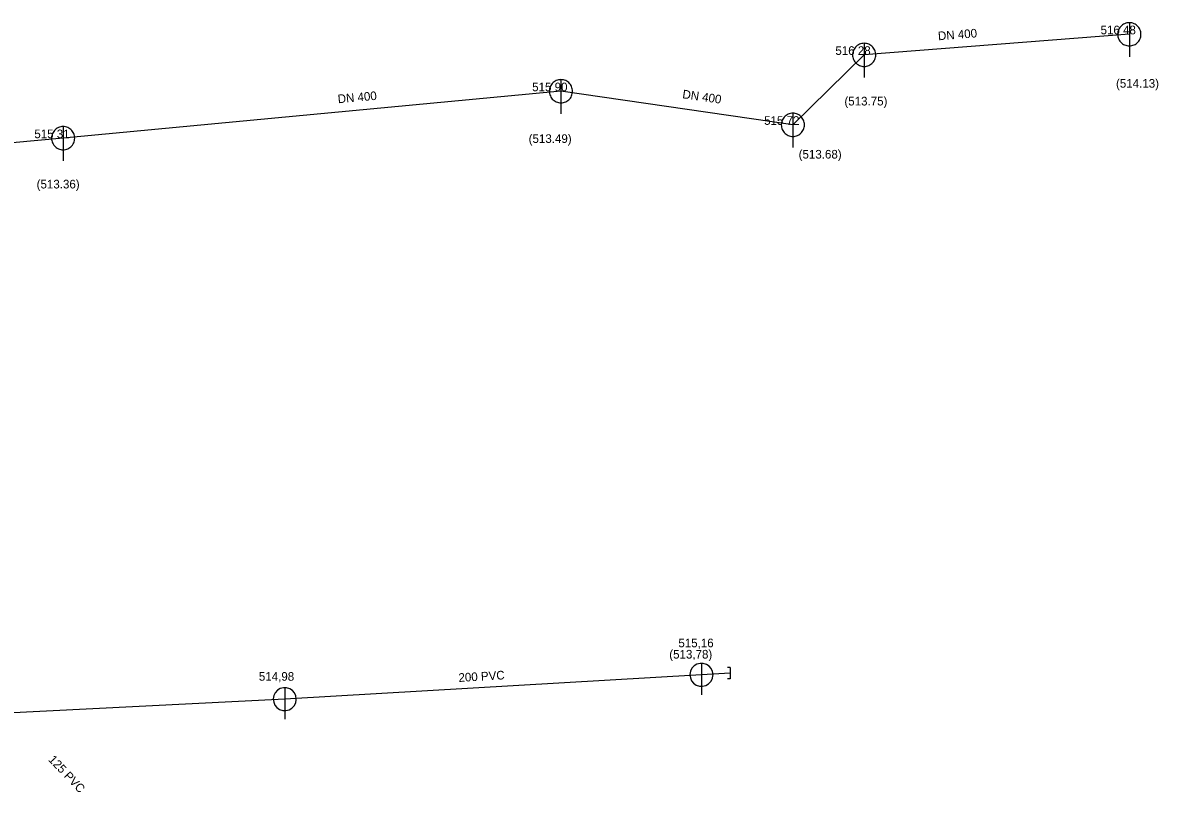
# Model space of a CAD drawing. Extents: x -476058 to -471893, y -1155786 to -1152000.
# Drawn here: x -474685.2 to -474586.5, y -1154195.9 to -1154129 of the extents above; entities that cross this region are included whole.
import ezdxf

# ---------------------------------------------------------------- set-up
doc = ezdxf.new("R2010")
doc.units = 0
for name, color, linetype in [('Vrstva 1', 7, 'Continuous'), ('Vrstva 10', 7, 'Continuous'), ('Vrstva 16', 7, 'Continuous'), ('Vrstva 18', 7, 'Continuous'), ('Vrstva 19', 7, 'Continuous'), ('Vrstva 3', 7, 'Continuous'), ('Vrstva 35', 7, 'Continuous'), ('Vrstva 4', 7, 'Continuous'), ('Vrstva 45', 7, 'Continuous')]:
    doc.layers.add(name, color=color, linetype=linetype)

msp = doc.modelspace()

# ---------------------------------------------------------------- linework, layer by layer
at = {"layer": 'Vrstva 1'}
for p, q in [((-474589.06, -1154130.02), (-474589.06, -1154130.02)), ((-474612.1, -1154131.81), (-474612.1, -1154131.81)), ((-474638.44, -1154134.97), (-474638.44, -1154134.97)), ((-474618.29, -1154137.89), (-474618.29, -1154137.89)), ((-474681.69, -1154139.05), (-474681.69, -1154139.05))]:
    msp.add_line(p, q, dxfattribs=at)
at = {"layer": 'Vrstva 10'}
for p, q in [((-474626.23, -1154184.69), (-474626.23, -1154187.438)), ((-474623.728, -1154185.044), (-474623.978, -1154185.044)), ((-474623.728, -1154185.044), (-474623.728, -1154186.044)), ((-474623.728, -1154186.044), (-474623.978, -1154186.044)), ((-474662.43, -1154186.81), (-474662.43, -1154189.558))]:
    msp.add_line(p, q, dxfattribs=at)
for points in [[(-474588.052, -1154130.02), (-474588.058, -1154129.915), (-474588.074, -1154129.811), (-474588.102, -1154129.709), (-474588.14, -1154129.61), (-474588.187, -1154129.516), (-474588.245, -1154129.428), (-474588.311, -1154129.346), (-474588.386, -1154129.271), (-474588.468, -1154129.205), (-474588.556, -1154129.147), (-474588.65, -1154129.1), (-474588.749, -1154129.062), (-474588.851, -1154129.034), (-474588.955, -1154129.018), (-474589.06, -1154129.012), (-474589.165, -1154129.018), (-474589.27, -1154129.034), (-474589.372, -1154129.062), (-474589.47, -1154129.1), (-474589.564, -1154129.147), (-474589.653, -1154129.205), (-474589.735, -1154129.271), (-474589.809, -1154129.346), (-474589.875, -1154129.428), (-474589.933, -1154129.516), (-474589.981, -1154129.61), (-474590.019, -1154129.709), (-474590.046, -1154129.811), (-474590.062, -1154129.915), (-474590.068, -1154130.02), (-474590.062, -1154130.125), (-474590.046, -1154130.23), (-474590.019, -1154130.332), (-474589.981, -1154130.43), (-474589.933, -1154130.524), (-474589.875, -1154130.613), (-474589.809, -1154130.695), (-474589.735, -1154130.769), (-474589.653, -1154130.835), (-474589.564, -1154130.893), (-474589.47, -1154130.941), (-474589.372, -1154130.979), (-474589.27, -1154131.006), (-474589.165, -1154131.022), (-474589.06, -1154131.028), (-474588.955, -1154131.022), (-474588.851, -1154131.006), (-474588.749, -1154130.979), (-474588.65, -1154130.941), (-474588.556, -1154130.893), (-474588.468, -1154130.835), (-474588.386, -1154130.769), (-474588.311, -1154130.695), (-474588.245, -1154130.613), (-474588.187, -1154130.524), (-474588.14, -1154130.43), (-474588.102, -1154130.332), (-474588.074, -1154130.23), (-474588.058, -1154130.125), (-474588.052, -1154130.02)], [(-474589.06, -1154129.012), (-474589.06, -1154131.988)], [(-474611.092, -1154131.81), (-474611.098, -1154131.705), (-474611.114, -1154131.601), (-474611.142, -1154131.499), (-474611.18, -1154131.4), (-474611.227, -1154131.306), (-474611.285, -1154131.218), (-474611.351, -1154131.136), (-474611.426, -1154131.061), (-474611.508, -1154130.995), (-474611.596, -1154130.937), (-474611.69, -1154130.89), (-474611.789, -1154130.852), (-474611.891, -1154130.824), (-474611.995, -1154130.808), (-474612.1, -1154130.802), (-474612.205, -1154130.808), (-474612.31, -1154130.824), (-474612.412, -1154130.852), (-474612.51, -1154130.89), (-474612.604, -1154130.937), (-474612.693, -1154130.995), (-474612.775, -1154131.061), (-474612.849, -1154131.136), (-474612.915, -1154131.218), (-474612.973, -1154131.306), (-474613.021, -1154131.4), (-474613.059, -1154131.499), (-474613.086, -1154131.601), (-474613.102, -1154131.705), (-474613.108, -1154131.81), (-474613.102, -1154131.915), (-474613.086, -1154132.02), (-474613.059, -1154132.122), (-474613.021, -1154132.22), (-474612.973, -1154132.314), (-474612.915, -1154132.403), (-474612.849, -1154132.485), (-474612.775, -1154132.559), (-474612.693, -1154132.625), (-474612.604, -1154132.683), (-474612.51, -1154132.731), (-474612.412, -1154132.769), (-474612.31, -1154132.796), (-474612.205, -1154132.812), (-474612.1, -1154132.818), (-474611.995, -1154132.812), (-474611.891, -1154132.796), (-474611.789, -1154132.769), (-474611.69, -1154132.731), (-474611.596, -1154132.683), (-474611.508, -1154132.625), (-474611.426, -1154132.559), (-474611.351, -1154132.485), (-474611.285, -1154132.403), (-474611.227, -1154132.314), (-474611.18, -1154132.22), (-474611.142, -1154132.122), (-474611.114, -1154132.02), (-474611.098, -1154131.915), (-474611.092, -1154131.81)], [(-474612.1, -1154130.802), (-474612.1, -1154133.778)], [(-474637.432, -1154134.97), (-474637.438, -1154134.865), (-474637.454, -1154134.761), (-474637.482, -1154134.659), (-474637.52, -1154134.56), (-474637.567, -1154134.466), (-474637.625, -1154134.378), (-474637.691, -1154134.296), (-474637.766, -1154134.221), (-474637.848, -1154134.155), (-474637.936, -1154134.097), (-474638.03, -1154134.05), (-474638.129, -1154134.012), (-474638.231, -1154133.984), (-474638.335, -1154133.968), (-474638.44, -1154133.962), (-474638.545, -1154133.968), (-474638.65, -1154133.984), (-474638.752, -1154134.012), (-474638.85, -1154134.05), (-474638.944, -1154134.097), (-474639.033, -1154134.155), (-474639.115, -1154134.221), (-474639.189, -1154134.296), (-474639.255, -1154134.378), (-474639.313, -1154134.466), (-474639.361, -1154134.56), (-474639.399, -1154134.659), (-474639.426, -1154134.761), (-474639.442, -1154134.865), (-474639.448, -1154134.97), (-474639.442, -1154135.075), (-474639.426, -1154135.18), (-474639.399, -1154135.282), (-474639.361, -1154135.38), (-474639.313, -1154135.474), (-474639.255, -1154135.563), (-474639.189, -1154135.645), (-474639.115, -1154135.719), (-474639.033, -1154135.785), (-474638.944, -1154135.843), (-474638.85, -1154135.891), (-474638.752, -1154135.929), (-474638.65, -1154135.956), (-474638.545, -1154135.972), (-474638.44, -1154135.978), (-474638.335, -1154135.972), (-474638.231, -1154135.956), (-474638.129, -1154135.929), (-474638.03, -1154135.891), (-474637.936, -1154135.843), (-474637.848, -1154135.785), (-474637.766, -1154135.719), (-474637.691, -1154135.645), (-474637.625, -1154135.563), (-474637.567, -1154135.474), (-474637.52, -1154135.38), (-474637.482, -1154135.282), (-474637.454, -1154135.18), (-474637.438, -1154135.075), (-474637.432, -1154134.97)], [(-474638.44, -1154133.962), (-474638.44, -1154136.938)], [(-474617.282, -1154137.89), (-474617.288, -1154137.785), (-474617.304, -1154137.681), (-474617.332, -1154137.579), (-474617.37, -1154137.48), (-474617.417, -1154137.386), (-474617.475, -1154137.298), (-474617.541, -1154137.216), (-474617.616, -1154137.141), (-474617.698, -1154137.075), (-474617.786, -1154137.017), (-474617.88, -1154136.97), (-474617.979, -1154136.932), (-474618.081, -1154136.904), (-474618.185, -1154136.888), (-474618.29, -1154136.882), (-474618.395, -1154136.888), (-474618.5, -1154136.904), (-474618.602, -1154136.932), (-474618.7, -1154136.97), (-474618.794, -1154137.017), (-474618.883, -1154137.075), (-474618.965, -1154137.141), (-474619.039, -1154137.216), (-474619.105, -1154137.298), (-474619.163, -1154137.386), (-474619.211, -1154137.48), (-474619.249, -1154137.579), (-474619.276, -1154137.681), (-474619.292, -1154137.785), (-474619.298, -1154137.89), (-474619.292, -1154137.995), (-474619.276, -1154138.1), (-474619.249, -1154138.202), (-474619.211, -1154138.3), (-474619.163, -1154138.394), (-474619.105, -1154138.483), (-474619.039, -1154138.565), (-474618.965, -1154138.639), (-474618.883, -1154138.705), (-474618.794, -1154138.763), (-474618.7, -1154138.811), (-474618.602, -1154138.849), (-474618.5, -1154138.876), (-474618.395, -1154138.892), (-474618.29, -1154138.898), (-474618.185, -1154138.892), (-474618.081, -1154138.876), (-474617.979, -1154138.849), (-474617.88, -1154138.811), (-474617.786, -1154138.763), (-474617.698, -1154138.705), (-474617.616, -1154138.639), (-474617.541, -1154138.565), (-474617.475, -1154138.483), (-474617.417, -1154138.394), (-474617.37, -1154138.3), (-474617.332, -1154138.202), (-474617.304, -1154138.1), (-474617.288, -1154137.995), (-474617.282, -1154137.89)], [(-474618.29, -1154136.882), (-474618.29, -1154139.858)], [(-474680.682, -1154139.05), (-474680.688, -1154138.945), (-474680.704, -1154138.841), (-474680.732, -1154138.739), (-474680.77, -1154138.64), (-474680.817, -1154138.546), (-474680.875, -1154138.458), (-474680.941, -1154138.376), (-474681.016, -1154138.301), (-474681.098, -1154138.235), (-474681.186, -1154138.177), (-474681.28, -1154138.13), (-474681.379, -1154138.092), (-474681.481, -1154138.064), (-474681.585, -1154138.048), (-474681.69, -1154138.042), (-474681.795, -1154138.048), (-474681.9, -1154138.064), (-474682.002, -1154138.092), (-474682.1, -1154138.13), (-474682.194, -1154138.177), (-474682.283, -1154138.235), (-474682.365, -1154138.301), (-474682.439, -1154138.376), (-474682.505, -1154138.458), (-474682.563, -1154138.546), (-474682.611, -1154138.64), (-474682.649, -1154138.739), (-474682.676, -1154138.841), (-474682.692, -1154138.945), (-474682.698, -1154139.05), (-474682.692, -1154139.155), (-474682.676, -1154139.26), (-474682.649, -1154139.362), (-474682.611, -1154139.46), (-474682.563, -1154139.554), (-474682.505, -1154139.643), (-474682.439, -1154139.725), (-474682.365, -1154139.799), (-474682.283, -1154139.865), (-474682.194, -1154139.923), (-474682.1, -1154139.971), (-474682.002, -1154140.009), (-474681.9, -1154140.036), (-474681.795, -1154140.052), (-474681.69, -1154140.058), (-474681.585, -1154140.052), (-474681.481, -1154140.036), (-474681.379, -1154140.009), (-474681.28, -1154139.971), (-474681.186, -1154139.923), (-474681.098, -1154139.865), (-474681.016, -1154139.799), (-474680.941, -1154139.725), (-474680.875, -1154139.643), (-474680.817, -1154139.554), (-474680.77, -1154139.46), (-474680.732, -1154139.362), (-474680.704, -1154139.26), (-474680.688, -1154139.155), (-474680.682, -1154139.05)], [(-474681.69, -1154138.042), (-474681.69, -1154141.018)], [(-474625.23, -1154185.69), (-474625.269, -1154185.411), (-474625.386, -1154185.154), (-474625.569, -1154184.939), (-474625.805, -1154184.785), (-474626.075, -1154184.702), (-474626.357, -1154184.698), (-474626.629, -1154184.773), (-474626.869, -1154184.921), (-474627.059, -1154185.13), (-474627.182, -1154185.384), (-474627.23, -1154185.662), (-474627.198, -1154185.943), (-474627.089, -1154186.203), (-474626.911, -1154186.422), (-474626.68, -1154186.584), (-474626.412, -1154186.674), (-474626.13, -1154186.686), (-474625.856, -1154186.618), (-474625.612, -1154186.477), (-474625.417, -1154186.273), (-474625.287, -1154186.023), (-474625.231, -1154185.746), (-474625.23, -1154185.69)], [(-474661.43, -1154187.81), (-474661.469, -1154187.531), (-474661.586, -1154187.274), (-474661.769, -1154187.059), (-474662.005, -1154186.905), (-474662.275, -1154186.822), (-474662.557, -1154186.818), (-474662.829, -1154186.893), (-474663.069, -1154187.041), (-474663.259, -1154187.25), (-474663.382, -1154187.504), (-474663.43, -1154187.782), (-474663.398, -1154188.063), (-474663.289, -1154188.323), (-474663.111, -1154188.542), (-474662.88, -1154188.704), (-474662.612, -1154188.794), (-474662.33, -1154188.806), (-474662.056, -1154188.738), (-474661.812, -1154188.597), (-474661.617, -1154188.393), (-474661.487, -1154188.143), (-474661.431, -1154187.866), (-474661.43, -1154187.81)]]:
    msp.add_lwpolyline(points, dxfattribs=at)
at = {"layer": 'Vrstva 35'}
msp.add_lwpolyline([(-474589.06, -1154130.02), (-474612.1, -1154131.81), (-474618.29, -1154137.89), (-474638.44, -1154134.97), (-474681.69, -1154139.05), (-474731.39, -1154143.62), (-474771.64, -1154147.16), (-474815, -1154151.05)], dxfattribs=at)
at = {"layer": 'Vrstva 45'}
for points in [[(-474626.23, -1154185.69), (-474662.43, -1154187.81)], [(-474623.728, -1154185.544), (-474626.23, -1154185.69)], [(-474662.43, -1154187.81), (-474687.18, -1154189.05)]]:
    msp.add_lwpolyline(points, dxfattribs=at)

# ---------------------------------------------------------------- texts
at = {"layer": 'Vrstva 16'}
for rotation, p in [(4.44082, (-474605.657, -1154130.544)), (5.12796, (-474657.8, -1154136.017)), (351.75449, (-474627.925, -1154135.571))]:
    msp.add_text('DN 400', height=0.75, rotation=rotation, dxfattribs=at).set_placement(p)
at = {"layer": 'Vrstva 18'}
msp.add_text('200 PVC', height=0.75, rotation=3.35161, dxfattribs=at).set_placement((-474647.322, -1154186.317))
at = {"layer": 'Vrstva 19'}
msp.add_text('125 PVC', height=0.75, rotation=313.43335, dxfattribs=at).set_placement((-474683.016, -1154193.112))
at = {"layer": 'Vrstva 3'}
for s, p in [('516 48 ', (-474591.56, -1154130.02)), ('516 28 ', (-474614.6, -1154131.81)), ('515 90 ', (-474640.94, -1154134.97)), ('515 72 ', (-474620.79, -1154137.89)), ('515 31 ', (-474684.19, -1154139.05)), ('515,16', (-474628.24, -1154183.3)), ('514,98', (-474664.684, -1154186.209))]:
    msp.add_text(s, height=0.75, dxfattribs=at).set_placement(p)
at = {"layer": 'Vrstva 4'}
for s, p in [('(514.13) ', (-474590.219, -1154134.66)), ('(513.75) ', (-474613.815, -1154136.205)), ('(513.49) ', (-474641.246, -1154139.463)), ('(513.68) ', (-474617.789, -1154140.821)), ('(513.36) ', (-474683.99, -1154143.418)), ('(513,78)', (-474629.03, -1154184.28))]:
    msp.add_text(s, height=0.75, dxfattribs=at).set_placement(p)

doc.saveas('drawing.dxf')
